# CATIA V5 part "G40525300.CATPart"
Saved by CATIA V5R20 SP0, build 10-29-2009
Part number: G40525300
Revision: 6
Definition: design
Nomenclature: G40525300
Source: made
Description: NOT SPECIFIED
Bounding box of the stored display mesh (mm): x -150 to 150, y -12.5 to 12.5, z -25 to 0
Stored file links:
  C:\Users\Raffaele\Desktop\3D X SITO CF\BOLEX\29-GUIDE STRIP REF 405\G40525300.CATPart
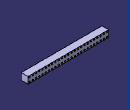
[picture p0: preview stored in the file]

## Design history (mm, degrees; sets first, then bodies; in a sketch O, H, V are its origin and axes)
Body1 "MANIFOLD_SOLID_BREP #7846" (main body)
  Solid1: solid without history
Body2 "MANIFOLD_SOLID_BREP #7984"
  Solid2: solid without history
Body3 "MANIFOLD_SOLID_BREP #8096"
  Solid3: solid without history
Body4 "MANIFOLD_SOLID_BREP #8208"
  Solid4: solid without history
Body5 "MANIFOLD_SOLID_BREP #8320"
  Solid5: solid without history
Body6 "MANIFOLD_SOLID_BREP #8432"
  Solid6: solid without history
Body7 "MANIFOLD_SOLID_BREP #8544"
  Solid7: solid without history
Body8 "MANIFOLD_SOLID_BREP #8656"
  Solid8: solid without history
Body9 "MANIFOLD_SOLID_BREP #8768"
  Solid9: solid without history
Body10 "MANIFOLD_SOLID_BREP #8880"
  Solid10: solid without history
Body11 "MANIFOLD_SOLID_BREP #8992"
  Solid11: solid without history
Body12 "MANIFOLD_SOLID_BREP #9104"
  Solid12: solid without history
Body13 "MANIFOLD_SOLID_BREP #9216"
  Solid13: solid without history
Body14 "MANIFOLD_SOLID_BREP #9328"
  Solid14: solid without history
Body15 "MANIFOLD_SOLID_BREP #9440"
  Solid15: solid without history
Body16 "MANIFOLD_SOLID_BREP #9552"
  Solid16: solid without history
Body17 "MANIFOLD_SOLID_BREP #9664"
  Solid17: solid without history
Body18 "MANIFOLD_SOLID_BREP #9776"
  Solid18: solid without history
Body19 "MANIFOLD_SOLID_BREP #9888"
  Solid19: solid without history
Body20 "MANIFOLD_SOLID_BREP #10000"
  Solid20: solid without history
Body21 "MANIFOLD_SOLID_BREP #10112"
  Solid21: solid without history
Body22 "MANIFOLD_SOLID_BREP #10224"
  Solid22: solid without history
Body23 "MANIFOLD_SOLID_BREP #10336"
  Solid23: solid without history
Body24 "MANIFOLD_SOLID_BREP #10448"
  Solid24: solid without history
Body25 "MANIFOLD_SOLID_BREP #10560"
  Solid25: solid without history
Body26 "MANIFOLD_SOLID_BREP #10672"
  Solid26: solid without history
Body27 "MANIFOLD_SOLID_BREP #10784"
  Solid27: solid without history
Body28 "MANIFOLD_SOLID_BREP #10896"
  Solid28: solid without history
Body29 "MANIFOLD_SOLID_BREP #11008"
  Solid29: solid without history
Body30 "MANIFOLD_SOLID_BREP #11120"
  Solid30: solid without history
Body31 "MANIFOLD_SOLID_BREP #11232"
  Solid31: solid without history
Body32 "MANIFOLD_SOLID_BREP #11344"
  Solid32: solid without history
Body33 "MANIFOLD_SOLID_BREP #11456"
  Solid33: solid without history
Body34 "MANIFOLD_SOLID_BREP #11568"
  Solid34: solid without history
Body35 "MANIFOLD_SOLID_BREP #11680"
  Solid35: solid without history
Body36 "MANIFOLD_SOLID_BREP #11792"
  Solid36: solid without history
Body37 "MANIFOLD_SOLID_BREP #11904"
  Solid37: solid without history
Body38 "MANIFOLD_SOLID_BREP #12016"
  Solid38: solid without history
Body39 "MANIFOLD_SOLID_BREP #12128"
  Solid39: solid without history
Body40 "MANIFOLD_SOLID_BREP #12240"
  Solid40: solid without history
Body41 "MANIFOLD_SOLID_BREP #12352"
  Solid41: solid without history
Body42 "MANIFOLD_SOLID_BREP #12464"
  Solid42: solid without history
Body43 "MANIFOLD_SOLID_BREP #12576"
  Solid43: solid without history
Body44 "MANIFOLD_SOLID_BREP #12688"
  Solid44: solid without history
Body45 "MANIFOLD_SOLID_BREP #12800"
  Solid45: solid without history
Body46 "MANIFOLD_SOLID_BREP #12912"
  Solid46: solid without history
Body47 "MANIFOLD_SOLID_BREP #13024"
  Solid47: solid without history
Body48 "MANIFOLD_SOLID_BREP #13136"
  Solid48: solid without history
Body49 "MANIFOLD_SOLID_BREP #13248"
  Solid49: solid without history
Body50 "MANIFOLD_SOLID_BREP #13360"
  Solid50: solid without history
Body51 "MANIFOLD_SOLID_BREP #13498"
  Solid51: solid without history
Body52 "MANIFOLD_SOLID_BREP #13636"
  Solid52: solid without history
Body53 "MANIFOLD_SOLID_BREP #13774"
  Solid53: solid without history
Body54 "MANIFOLD_SOLID_BREP #13912"
  Solid54: solid without history
Body55 "MANIFOLD_SOLID_BREP #14050"
  Solid55: solid without history
Body56 "MANIFOLD_SOLID_BREP #14188"
  Solid56: solid without history
Body57 "MANIFOLD_SOLID_BREP #14326"
  Solid57: solid without history
Body58 "MANIFOLD_SOLID_BREP #14464"
  Solid58: solid without history
Body59 "MANIFOLD_SOLID_BREP #14602"
  Solid59: solid without history
Body60 "MANIFOLD_SOLID_BREP #14740"
  Solid60: solid without history
Body61 "MANIFOLD_SOLID_BREP #14878"
  Solid61: solid without history
Body62 "MANIFOLD_SOLID_BREP #15016"
  Solid62: solid without history
Body63 "MANIFOLD_SOLID_BREP #15154"
  Solid63: solid without history
Body64 "MANIFOLD_SOLID_BREP #15292"
  Solid64: solid without history
Body65 "MANIFOLD_SOLID_BREP #15430"
  Solid65: solid without history
Body66 "MANIFOLD_SOLID_BREP #15568"
  Solid66: solid without history
Body67 "MANIFOLD_SOLID_BREP #15706"
  Solid67: solid without history
Body68 "MANIFOLD_SOLID_BREP #15844"
  Solid68: solid without history
Body69 "MANIFOLD_SOLID_BREP #15982"
  Solid69: solid without history
Body70 "MANIFOLD_SOLID_BREP #16120"
  Solid70: solid without history
Body71 "MANIFOLD_SOLID_BREP #16258"
  Solid71: solid without history
Body72 "MANIFOLD_SOLID_BREP #16396"
  Solid72: solid without history
Body73 "MANIFOLD_SOLID_BREP #16534"
  Solid73: solid without history
Body74 "MANIFOLD_SOLID_BREP #16646"
  Solid74: solid without history
Body75 "MANIFOLD_SOLID_BREP #16758"
  Solid75: solid without history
